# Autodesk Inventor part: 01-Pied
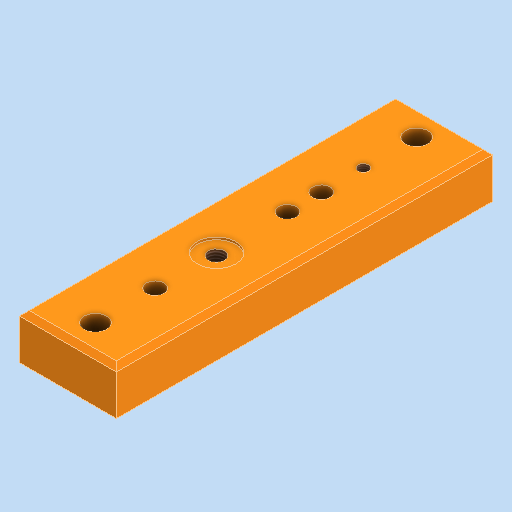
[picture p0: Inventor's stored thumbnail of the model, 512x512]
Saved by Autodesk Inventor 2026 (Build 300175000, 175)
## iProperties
Created: 2025-12
Part Number: 01-Pied
Material: Générique
Document SubType Name: Modeling
Designer: thierry.jost
Density: 1 g/cm^3
Appearance: Orange
Author: thierry.jost
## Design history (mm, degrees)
sketch "Esquisse1"
  geometry: L1 (2.005, 103.667)-(30.005, 103.667); L2 (30.005, 103.667)-(30.005, -129.333); L3 (30.005, -129.333)-(2.005, -129.333); L4 (2.005, -129.333)-(2.005, 103.667); 1 further point
  constraints: 8 end point, 3 perpendicular, 1 horizontal
  dimensions: "d0" = 233 distance of L1.end L2.end; "d1" = 28 distance of L1.start L1.end
extrude "Extrusion1" new body sketch "Esquisse1" stored distance "d2" = 60; taper "d3" = 0 deg
sketch "Esquisse2"
  geometry: L1 (0, 233)-(60, 233) reference; L2 (60, 0)-(0, 0) reference; L3 (48.411, 196)-(8.411, 196); L4 (8.411, 196)-(8.411, 43); L5 (8.411, 43)-(48.411, 43); L6 (48.411, 43)-(48.411, 196); 1 further point
  constraints: 8 end point, 2 parallel, 1 horizontal, 1 perpendicular
  dimensions: "d10" = 40 distance of L4.end L5.end; "d26" = 37 distance between parallel lines of L1 L3
extrude "Extrusion2" cut sketch "Esquisse2" distance "d12" = 5; taper "d13" = 0 deg
sketch "Esquisse3"
  geometry: L1 (48.411, 196)-(48.411, 43) reference; L2 (8.411, 43)-(8.411, 196) reference; L3 (48.411, 43)-(8.411, 43); L4 (8.411, 43)-(8.411, 121); L5 (8.411, 121)-(48.411, 121); L6 (48.411, 121)-(48.411, 43); 3 further points
  constraints: 8 end point, 2 parallel, 1 horizontal, 1 perpendicular, 1 point on line
  dimensions: "d14" = 78 distance between parallel lines of L3 L5
extrude "Extrusion3" cut sketch "Esquisse3" distance "d15" = 7; taper "d16" = 0 deg
sketch "Esquisse4"
  geometry: L1 (0, 233)-(60, 233) reference; L2 (60, 233)-(60, 0) reference; 2 further points
  dimensions: "d24" = 54 distance from line of point (30, 179) L1; "d25" = 30 distance from line of point (30, 179) L2
hole "Perçage1" sketch "Esquisse4" diameter "d17" = 11; stored, may be unused: countersink angle "d21" = 90 deg, drill point angle "d23" = 118 deg; dims "d18" = 6, "d19" = 21, "d20" = 11, "d22" = 5
sketch "Esquisse5"
  geometry: L1 (60, 233)-(60, 0) reference; L2 (0, 233)-(60, 233) reference; 2 further points
  dimensions: "d34" = 30 distance from line of point (30, 141) L1; "d35" = 92 distance from line of point (30, 141) L2
hole "Perçage2" sketch "Esquisse5" at (30, 141) diameter "d27" = 10.106; stored, may be unused: countersink angle "d31" = 90 deg, drill point angle "d33" = 118 deg; dims "d28" = 24, "d29" = 20, "d30" = 11, "d32" = 27.3
sketch "Esquisse6"
  geometry: L1 (60, 233)-(60, 0) reference; L2 (0, 233)-(60, 233) reference; 2 further points
  dimensions: "d43" = 30 distance from line of point (30, 216) L1; "d44" = 17 distance from line of point (30, 216) L2
hole "Perçage3" sketch "Esquisse6" at (30, 216) diameter "d36" = 14; stored, may be unused: countersink angle "d40" = 90 deg, drill point angle "d42" = 118 deg; dims "d37" = 20, "d38" = 4, "d39" = 2, "d41" = 8
sketch "Esquisse7"
  geometry: L1 (60, 233)-(60, 0) reference; L2 (60, 0)-(0, 0) reference; 2 further points
  dimensions: "d52" = 30 distance from line of point (30, 17) L1; "d53" = 17 distance from line of point (30, 17) L2
hole "Perçage4" sketch "Esquisse7" at (30, 17) diameter "d45" = 14; stored, may be unused: countersink angle "d49" = 90 deg, drill point angle "d51" = 118 deg; dims "d46" = 6, "d47" = 4, "d48" = 2, "d50" = 8
sketch "Esquisse8"
  geometry: L1 (60, 0)-(0, 0) reference; L2 (60, 233)-(60, 0) reference; 2 further points
  dimensions: "d61" = 76 distance from line of L1 point (30, 76); "d62" = 30 distance from line of point (30, 76) L2
hole "Perçage5" sketch "Esquisse8" at (30, 76) diameter "d54" = 11; stored, may be unused: countersink angle "d58" = 90 deg, drill point angle "d60" = 118 deg; dims "d55" = 6, "d56" = 4, "d57" = 2, "d59" = 8
sketch "Esquisse9"
  geometry: L1 (60, 233)-(60, 0) reference; L2 (60, 0)-(0, 0) reference; 2 further points
  dimensions: "d70" = 30 distance from line of L1 point (30, 97); "d71" = 97 distance from line of L2 point (30, 97)
hole "Perçage6" sketch "Esquisse9" at (30, 97) diameter "d63" = 11; stored, may be unused: countersink angle "d67" = 90 deg, drill point angle "d69" = 118 deg; dims "d64" = 6, "d65" = 21, "d66" = 2, "d68" = 8
sketch "Esquisse10"
  geometry: L1 (60, 233)-(60, 0) reference; L2 (60, 0)-(0, 0) reference; 2 further points
  dimensions: "d79" = 30 distance from line of L1 point (30, 50); "d80" = 50 distance from line of L2 point (30, 50)
hole "Perçage7" sketch "Esquisse10" at (30, 50) diameter "d72" = 6.647; stored, may be unused: countersink angle "d76" = 90 deg, drill point angle "d78" = 118 deg; dims "d73" = 16, "d74" = 20, "d75" = 2, "d77" = 8
fillet "Congé1" dims "d81" = 5
fillet "Congé2" dims "d82" = 5
chamfer "Chanfrein1" distance "d83" = 3; stored, may be unused: second distance "d84" = 2, angle "d85" = 45 deg
sketch "Esquisse11"
  geometry: C1 r 5.053 at (27, 89) reference; C2 r 12 at (27, 89); 1 further point
  constraints: 1 centre point, 1 coincident
  dimensions: "d86" = 24 diameter of C2
extrude "Extrusion4" cut sketch "Esquisse11" distance "d87" = 1.5; taper "d88" = 0 deg
feature "ʂ耀ʄ耀ʆ耀ʈ耀ʊ耀ʌ耀ʎ耀ʐ耀" dims "d0" = 233, "d1" = 28, "d2" = 60, "d3" = 0, "d10" = 40, "d12" = 5, "d13" = 0, "d14" = 78, "d15" = 7, "d16" = 0, "d17" = 11, "d18" = 6, "d19" = 21, "d20" = 11, "d21" = 90 deg, "d22" = 5, "d23" = 118 deg, "d24" = 54, "d25" = 30, "d26" = 37, "d27" = 10.106, "d28" = 24, "d29" = 20, "d30" = 11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
node "Solide1"
